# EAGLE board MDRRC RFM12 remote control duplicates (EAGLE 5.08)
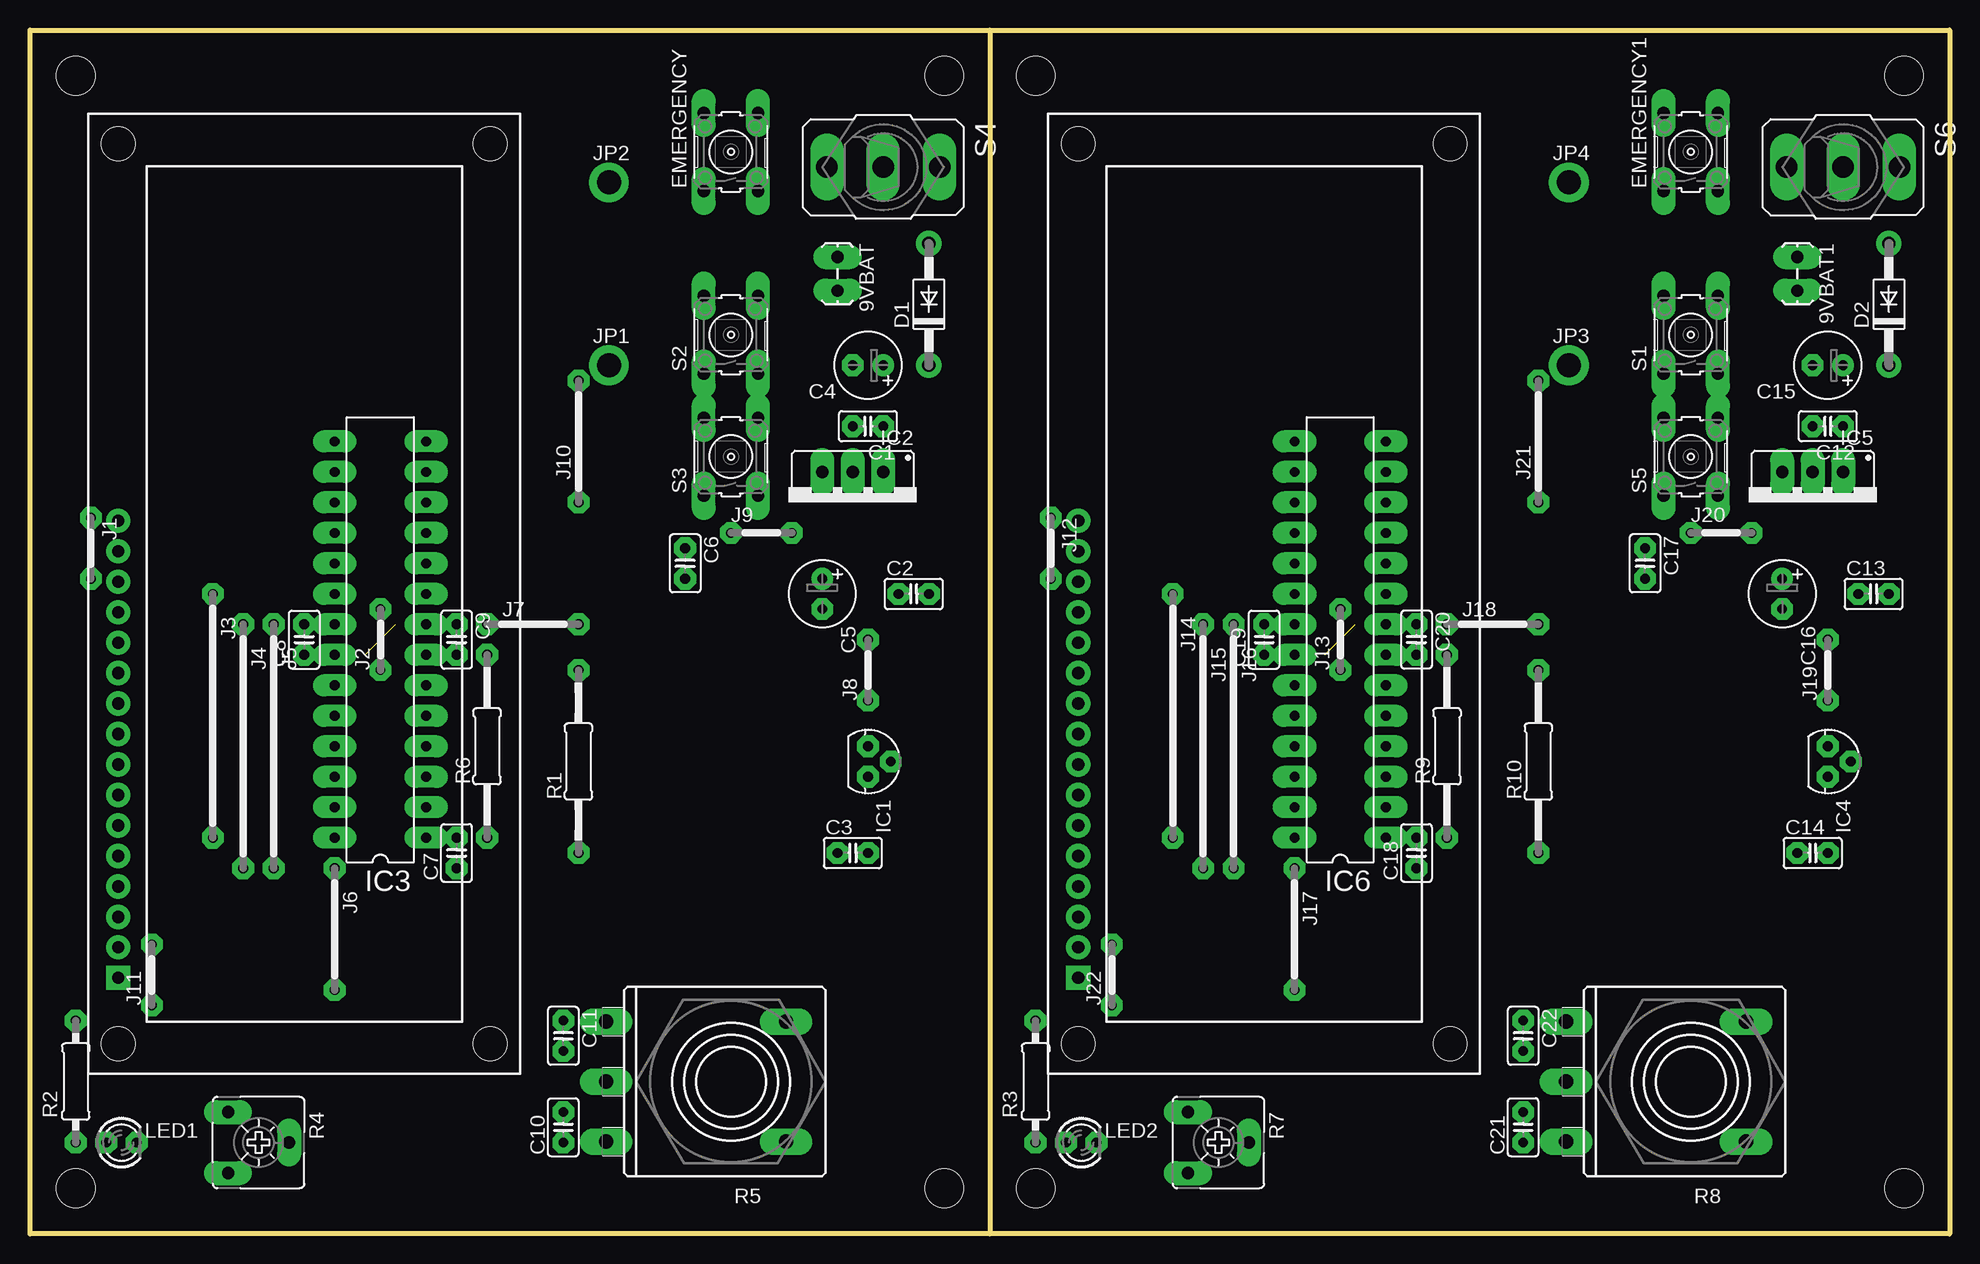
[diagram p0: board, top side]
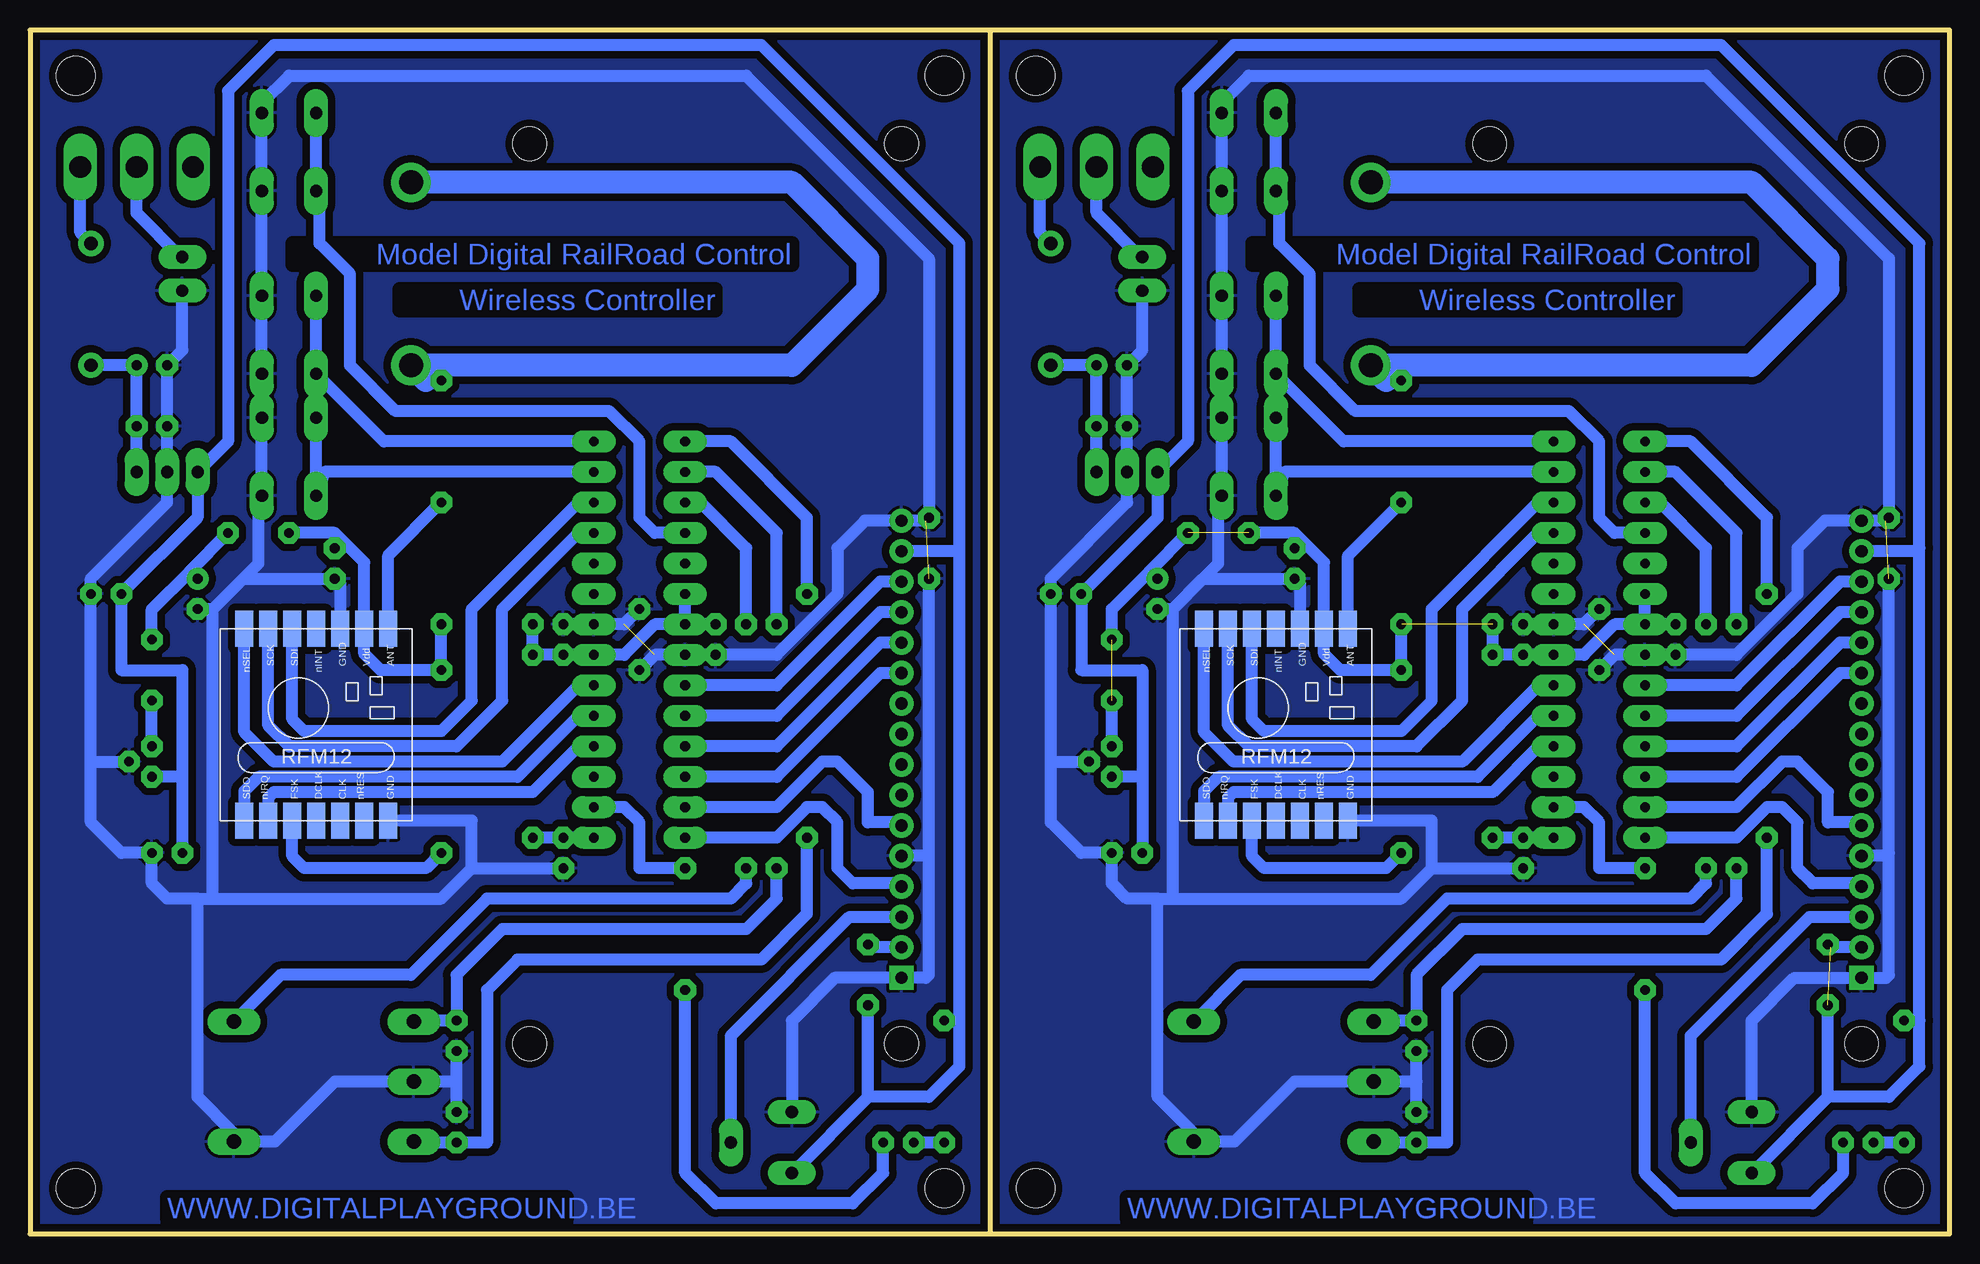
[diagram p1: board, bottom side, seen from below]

Size 160.02 x 100.33 mm. Coordinates in mm from the lower left corner, seen from the top.
Outline: 80.01,100.33 0,100.33 0,0 80.01,0
Outline: 80.01,100.33 160.02,100.33 160.02,0 80.01,0
Outline: 80.01,100.33 80.01,0
Copper layers (1*16): Top 0.8mm / dielectric 1.3mm / Bottom 0.8mm
Design rules "DRC settings smallest": minimum track width 0.8mm, minimum drill 24mil, track to track 0.2mm, track to pad 0.2mm, pad to pad 0.2mm, via to via 0.2mm, smd to smd 8mil, copper to edge 0.3mm, drill to drill 0.3mm, minimum pad ring 0.5mm, minimum via ring 1mm, stop-mask expansion 4mil, vias tented up to drill 0mil, thermal gap 10mil
Holes 3.2 mm at 3.81,96.52 3.81,3.81 76.2,3.81 76.2,96.52 83.82,96.52 83.82,3.81 156.21,3.81 156.21,96.52

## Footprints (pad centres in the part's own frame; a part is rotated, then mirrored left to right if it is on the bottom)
1X02_LOCK_LONGPADS = drill 1.016 long: 1 -0.127,0; 2 2.667,0
C025-025X050 = drill 0.813 octagon: 1 -1.27,0; 2 1.27,0
E2,5-6 = drill 0.813 pad 1.6 round: + -1.27,0 | drill 0.813 pad 1.6 octagon: - 1.27,0
DO41-10 = drill 1.118 round: A 5.08,0; C -5.08,0
B3F-10XX = drill 1.016 long: 1 -3.251,2.261; 2 3.251,2.261; 3 -3.251,-2.261; 4 3.251,-2.261
78LXX = drill 0.813 octagon: GND 0,1.905; IN 1.27,0; OUT -1.27,0
78XXS = drill 1.016 long: GND 0,-2.54; IN -2.54,-2.54; OUT 2.54,-2.54
DIL28-3 = drill 0.813 long: 1 -16.51,-3.81; 2 -13.97,-3.81; 3 -11.43,-3.81; 4 -8.89,-3.81; 5 -6.35,-3.81; 6 -3.81,-3.81; 7 -1.27,-3.81; 8 1.27,-3.81; 9 3.81,-3.81; 10 6.35,-3.81; 11 8.89,-3.81; 12 11.43,-3.81; 13 13.97,-3.81; 14 16.51,-3.81; 15 16.51,3.81; 16 13.97,3.81; 17 11.43,3.81; 18 8.89,3.81; 19 6.35,3.81; 20 3.81,3.81; 21 1.27,3.81; 22 -1.27,3.81; 23 -3.81,3.81; 24 -6.35,3.81; 25 -8.89,3.81; 26 -11.43,3.81; 27 -13.97,3.81; 28 -16.51,3.81
05 = drill 0.813 pad 1.6 octagon: 1 -2.54,0; 2 2.54,0
20 = drill 0.813 pad 1.6 octagon: 1 -10.16,0; 2 10.16,0
10 = drill 0.813 pad 1.6 octagon: 1 -5.08,0; 2 5.08,0
07 = drill 0.813 pad 1.6 octagon: 1 -3.81,0; 2 3.81,0
1X01_2MM = drill 2 pad 3.302 round: 1 0,0
LED3MM = drill 0.813 octagon: A -1.27,0; K 1.27,0
0207/15 = drill 0.813 octagon: 1 -7.62,0; 2 7.62,0
0207/10 = drill 0.813 octagon: 1 -5.08,0; 2 5.08,0
CA6V = drill 1.016 long: A -2.54,-2.54; E 2.54,-2.54; S 0,2.54
PC16SV = drill 1.2 long: 1A -5,10.4; 1E 5,10.4; 1S 0,10.4; S1 -5,-4.6; S2 5,-4.6
M9040P = drill 1.803 long: 1 0,4.699; 2 0,0; 3 0,-4.699
RFM12 = smd 1.5 x 3: 1 -5,-10; 2 -3,-10; 3 -1,-10; 4 1,-10; 5 3,-10; 6 5,-10; 7 7,-10; 8 7,6; 9 5,6; 10 3,6; 11 1,6; 12 -1,6; 13 -3,6; 14 -5,6
LCD-16X2 = drill 1.016 square: 1 -32,15.5 | drill 1.016 round: 2 -29.46,15.5; 3 -26.92,15.5; 4 -24.38,15.5; 5 -21.84,15.5; 6 -19.3,15.5; 7 -16.76,15.5; 8 -14.22,15.5; 9 -11.68,15.5; 10 -9.14,15.5; 11 -6.6,15.5; 12 -4.06,15.5; 13 -1.52,15.5; 14 1.02,15.5; 15 3.56,15.5; 16 6.1,15.5 | hole 2.8: -37.5,15.5; -37.5,-15.5; 37.5,15.5; 37.5,-15.5

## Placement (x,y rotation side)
9VBAT  [1X02_LOCK_LONGPADS]  67.31,81.28 270 top
9VBAT1  [1X02_LOCK_LONGPADS]  147.32,81.28 270 top
C1  100nF  [C025-025X050]  69.85,67.31 180 top
C2  100nF  [C025-025X050]  73.66,53.34 0 top
C3  100nF  [C025-025X050]  68.58,31.75 0 top
C4  10uF  [E2,5-6]  69.85,72.39 180 top
C5  10uF  [E2,5-6]  66.04,53.34 270 top
C6  100nF  [C025-025X050]  54.61,55.88 270 top
C7  100nF  [C025-025X050]  35.56,31.75 90 top
C8  100nF  [C025-025X050]  22.86,49.53 90 top
C9  100nF  [C025-025X050]  35.56,49.53 270 top
C10  100nF  [C025-025X050]  44.45,8.89 90 top
C11  100nF  [C025-025X050]  44.45,16.51 270 top
C12  100nF  [C025-025X050]  149.86,67.31 180 top
C13  100nF  [C025-025X050]  153.67,53.34 0 top
C14  100nF  [C025-025X050]  148.59,31.75 0 top
C15  10uF  [E2,5-6]  149.86,72.39 180 top
C16  10uF  [E2,5-6]  146.05,53.34 270 top
C17  100nF  [C025-025X050]  134.62,55.88 270 top
C18  100nF  [C025-025X050]  115.57,31.75 90 top
C19  100nF  [C025-025X050]  102.87,49.53 90 top
C20  100nF  [C025-025X050]  115.57,49.53 270 top
C21  100nF  [C025-025X050]  124.46,8.89 90 top
C22  100nF  [C025-025X050]  124.46,16.51 270 top
D1  1N4004  [DO41-10]  74.93,77.47 90 top
D2  1N4004  [DO41-10]  154.94,77.47 90 top
EMERGENCY  [B3F-10XX]  58.42,90.17 90 top
EMERGENCY1  [B3F-10XX]  138.43,90.17 90 top
IC1  78L33  [78LXX]  69.85,39.37 270 top
IC2  7805  [78XXS]  68.58,60.96 180 top
IC3  MEGA8-P  [DIL28-3]  29.21,49.53 90 top
IC4  78L33  [78LXX]  149.86,39.37 270 top
IC5  7805  [78XXS]  148.59,60.96 180 top
IC6  MEGA8-P  [DIL28-3]  109.22,49.53 90 top
J1  J5MM  [05]  5.08,57.15 270 top
J2  J5MM  [05]  29.21,49.53 90 top
J3  J20MM  [20]  15.24,43.18 270 top
J4  J20MM  [20]  17.78,40.64 270 top
J5  J20MM  [20]  20.32,40.64 270 top
J6  J10MM  [10]  25.4,25.4 270 top
J7  J7MM  [07]  41.91,50.8 0 top
J8  J5MM  [05]  69.85,46.99 90 top
J9  J5MM  [05]  60.96,58.42 0 top
J10  J10MM  [10]  45.72,66.04 90 top
J11  J5MM  [05]  10.16,21.59 90 top
J12  J5MM  [05]  85.09,57.15 270 top
J13  J5MM  [05]  109.22,49.53 90 top
J14  J20MM  [20]  95.25,43.18 270 top
J15  J20MM  [20]  97.79,40.64 270 top
J16  J20MM  [20]  100.33,40.64 270 top
J17  J10MM  [10]  105.41,25.4 270 top
J18  J7MM  [07]  121.92,50.8 0 top
J19  J5MM  [05]  149.86,46.99 90 top
J20  J5MM  [05]  140.97,58.42 0 top
J21  J10MM  [10]  125.73,66.04 90 top
J22  J5MM  [05]  90.17,21.59 90 top
JP1  M01PTH_2MM  [1X01_2MM]  48.26,72.39 0 top
JP2  M01PTH_2MM  [1X01_2MM]  48.26,87.63 0 top
JP3  M01PTH_2MM  [1X01_2MM]  128.27,72.39 0 top
JP4  M01PTH_2MM  [1X01_2MM]  128.27,87.63 0 top
LED1  [LED3MM]  7.62,7.62 0 top
LED2  [LED3MM]  87.63,7.62 0 top
R1  1K  [0207/15]  45.72,39.37 90 top
R2  1K  [0207/10]  3.81,12.7 90 top
R3  1K  [0207/10]  83.82,12.7 90 top
R4  [CA6V]  19.05,7.62 270 top
R5  PC16SV  [PC16SV]  58.42,12.7 90 top
R6  10K  [0207/15]  38.1,40.64 90 top
R7  [CA6V]  99.06,7.62 270 top
R8  PC16SV  [PC16SV]  138.43,12.7 90 top
R9  10K  [0207/15]  118.11,40.64 90 top
R10  1K  [0207/15]  125.73,39.37 90 top
S1  [B3F-10XX]  138.43,74.93 90 top
S2  [B3F-10XX]  58.42,74.93 90 top
S3  [B3F-10XX]  58.42,64.77 90 top
S4  [M9040P]  71.12,88.9 270 top
S5  [B3F-10XX]  138.43,64.77 90 top
S6  [M9040P]  151.13,88.9 270 top
U$1  RFM12_SMDSMD  [RFM12]  57.15,44.45 0 bottom
U$2  LCD-16X2  [LCD-16X2]  22.86,53.34 90 top
U$3  RFM12_SMDSMD  [RFM12]  137.16,44.45 0 bottom
U$4  LCD-16X2  [LCD-16X2]  102.87,53.34 90 top

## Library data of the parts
9VBAT 9VBAT1 JP1-JP4 U$2 U$4 = SparkFun
C1-C3 C6-C14 C17-C22 R1 R6 R9 R10 = rcl
C4 C5 C15 C16 R2 R3 = resistor
D1 D2 = diode
EMERGENCY EMERGENCY1 S1-S3 S5 = switch-omron
IC1 IC2 IC4 IC5 = v-reg
IC3 IC6 = atmel
J1-J22 = jumper
LED1 LED2 = led
R4 R7 = pot
R5 R8 = piher
S4 S6 = switch
U$1 U$3 = rfm_12

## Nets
+3V1: C16.+ C17.1 C19.2 C20.2 IC4.OUT IC6.7 IC6.20 IC6.21 J18.1 J18.2 J19.1 J19.2 J20.1 J20.2 R9.2 R10.2 U$3.9
+3V3: C5.+ C6.1 C8.2 C9.2 IC1.OUT IC3.7 IC3.20 IC3.21 J7.1 J7.2 J8.1 J8.2 J9.1 J9.2 R1.2 R6.2 U$1.9
+5V: C2.1 C3.1 IC1.IN IC2.OUT J11.1 J11.2 R2.2 R4.E U$2.2 U$2.15
+5V1: C13.1 C14.1 IC4.IN IC5.OUT J22.1 J22.2 R3.2 R7.E U$4.2 U$4.15
GND: 9VBAT.2 C1.2 C2.2 C3.2 C4.- C5.- C6.2 C7.1 C8.1 C9.1 C10.2 C11.2 EMERGENCY.3 EMERGENCY.4 IC1.GND IC2.GND IC3.8 IC3.22 J1.1 J1.2 J2.1 J2.2 R4.A R5.1S R5.S1 S2.3 S2.4 S3.3 S3.4 U$1.7 U$1.10 U$2.1 U$2.5 U$2.16
GND1: 9VBAT1.2 C12.2 C13.2 C14.2 C15.- C16.- C17.2 C18.1 C19.1 C20.1 C21.2 C22.2 EMERGENCY1.3 EMERGENCY1.4 IC4.GND IC5.GND IC6.8 IC6.22 J12.1 J12.2 J13.1 J13.2 R7.A R8.1S R8.S1 S1.3 S1.4 S5.3 S5.4 U$3.7 U$3.10 U$4.1 U$4.5 U$4.16
N$1: D1.A S4.1
N$2: C1.1 C4.+ D1.C IC2.IN
N$3: 9VBAT.1 S4.2
N$4: IC3.2 J6.1
N$5: C7.2 IC3.1 R6.1
N$6: R4.S U$2.3
N$7: J5.2 R5.S2
N$8: LED1.A R2.1
N$9: J6.2 LED1.K
N$10: J10.2 JP1.1 JP2.1
N$11: R1.1 U$1.3
N$12: IC3.28 U$2.4
N$13: IC3.27 U$2.6
N$14: IC3.23 U$2.14
N$15: IC3.24 U$2.13
N$16: IC3.25 U$2.12
N$17: IC3.26 U$2.11
N$18: IC3.12 U$1.12
N$19: IC3.5 U$1.1
N$20: IC3.11 U$1.13
N$21: IC3.6 U$1.14
N$22: IC3.4 U$1.2
N$23: J10.1 U$1.8
N$24: EMERGENCY.1 EMERGENCY.2 IC3.18
N$25: IC3.15 J3.1
N$26: IC3.14 S2.1 S2.2
N$27: IC3.13 S3.1 S3.2
N$28: IC3.16 J4.1
N$29: IC3.17 J5.1
N$30: C10.1 J3.2 R5.1A
N$31: C11.1 J4.2 R5.1E
N$32: C12.1 C15.+ D2.C IC5.IN
N$33: J21.2 JP3.1 JP4.1
N$34: R10.1 U$3.3
N$35: C18.2 IC6.1 R9.1
N$36: LED2.A R3.1
N$37: IC6.28 U$4.4
N$38: IC6.27 U$4.6
N$39: IC6.23 U$4.14
N$40: IC6.24 U$4.13
N$41: IC6.25 U$4.12
N$42: IC6.26 U$4.11
N$43: IC6.12 U$3.12
N$44: IC6.5 U$3.1
N$45: IC6.11 U$3.13
N$46: IC6.6 U$3.14
N$47: IC6.4 U$3.2
N$48: R7.S U$4.3
N$49: J16.2 R8.S2
N$50: EMERGENCY1.1 EMERGENCY1.2 IC6.18
N$51: IC6.14 S1.1 S1.2
N$52: IC6.13 S5.1 S5.2
N$53: IC6.15 J14.1
N$54: IC6.16 J15.1
N$55: IC6.17 J16.1
N$56: C21.1 J14.2 R8.1A
N$57: C22.1 J15.2 R8.1E
N$58: IC6.2 J17.1
N$59: J17.2 LED2.K
N$60: J21.1 U$3.8
N$61: D2.A S6.1
N$62: 9VBAT1.1 S6.2

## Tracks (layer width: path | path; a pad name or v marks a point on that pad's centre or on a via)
+3V1
  Bottom 1.016: C19.2 IC6.21 | IC6.21 IC6.20 | IC6.21 107.95,50.8 110.49,48.26 IC6.7 C20.2 R9.2 J18.1 | J18.2 R10.2 130.81,46.99 132.16,48.34 U$3.9 132.16,55.96 134.62,58.42 | IC4.OUT J19.1 | J19.2 149.86,52.07 146.69,55.24 | 146.69,55.24 J20.2 | 146.69,55.24 C16.+ | 134.62,58.42 J20.1 | 134.62,58.42 C17.1
+3V3  (3 unrouted)
  Bottom 1.016: C8.2 IC3.21 | IC3.21 IC3.20 | IC3.21 27.94,50.8 30.48,48.26 IC3.7 C9.2 R6.2 J7.1 | J7.2 R1.2 50.8,46.99 52.15,48.34 U$1.9 52.15,55.96 54.61,58.42 | IC1.OUT J8.1 | J8.2 69.85,52.07 66.67,55.24 | 66.67,55.24 J9.2 | 66.67,55.24 C5.+ | 54.61,58.42 J9.1 | 54.61,58.42 C6.1
+5V  (1 unrouted)
  Bottom 1.016: 2.54,17.78 2.54,13.97 5.08,11.43 10.16,11.43 | 2.54,17.78 2.54,57.15 | 67.31,38.1 67.31,46.99 72.39,46.99 C2.1 66.04,59.69 IC2.OUT 63.5,66.04 63.5,95.25 59.69,99.06 19.05,99.06 2.54,82.55 2.54,57.15 | 67.31,38.1 IC1.IN | 67.31,38.1 C3.1 | U$2.15 2.79,56.9 2.54,57.15 | 7.87,23.88 U$2.2 9.91,23.88 J11.2 | 10.16,11.43 R4.E | 10.16,11.43 J11.1 | 2.54,17.78 R2.2
+5V1
  Bottom 1.016: 82.55,17.78 82.55,13.97 85.09,11.43 90.17,11.43 | 82.55,17.78 82.55,57.15 | 147.32,38.1 147.32,46.99 152.4,46.99 C13.1 146.05,59.69 IC5.OUT 143.51,66.04 143.51,95.25 139.7,99.06 99.06,99.06 82.55,82.55 82.55,57.15 | 147.32,38.1 IC4.IN | 147.32,38.1 C14.1 | U$4.15 82.8,56.9 82.55,57.15 | 87.88,23.88 U$4.2 89.92,23.88 J22.2 | 90.17,11.43 R7.E | 90.17,11.43 J22.1 | 82.55,17.78 R3.2
GND  (2 unrouted)
  Bottom 1.016: J2.2 30.48,50.8 IC3.8 C9.1 | J2.1 27.94,48.26 IC3.22 C8.1 17.78,48.26 12.7,53.34 12.7,57.15 10.41,59.44 U$2.16 5.33,59.44 J1.1 5.08,81.28 20.32,96.52 58.42,96.52 60.68,94.26 S3.3 | C10.2 44.45,12.7 | 44.45,12.7 C11.2 | 44.45,12.7 R5.1S 54.61,12.7 59.61,7.7 R5.S1 63.02,8.41 66.04,11.43 66.04,27.94 | EMERGENCY.4 EMERGENCY.3 S2.4 S2.3 S3.4 S3.3 | U$1.7 43.18,34.45 43.18,30.48 | S3.3 60.96,62.51 60.96,55.88 62.23,54.61 | 64.77,52.07 62.23,54.61 | 64.77,52.07 C5.- | 64.77,27.94 64.77,52.07 | 74.93,39.37 IC1.GND | 74.93,39.37 74.93,34.29 72.39,31.75 C3.2 69.85,29.21 68.58,27.94 66.04,27.94 | 66.04,27.94 64.77,27.94 | 74.93,39.37 C2.2 74.93,54.61 68.58,60.96 IC2.GND C1.2 C4.- 67.31,73.66 9VBAT.2 | 64.77,27.94 45.72,27.94 43.18,30.48 | 5.08,31.75 5.08,21.59 5.33,21.34 U$2.1 12.95,21.34 16.51,17.78 R4.A | U$2.5 5.33,31.5 5.08,31.75 | 5.08,31.75 J1.2 | 43.18,30.48 C7.1 | U$1.10 54.15,54.15 C6.2 62.23,54.61
  pour Bottom (isolate 0.61): 0,100.33 80.01,100.33 80.01,0 0,0
  pour Bottom (isolate 0.61): 0,100.33 80.01,100.33 80.01,0 0,0
GND1  (2 unrouted)
  Bottom 1.016: J13.2 110.49,50.8 IC6.8 C20.1 | J13.1 107.95,48.26 IC6.22 C19.1 97.79,48.26 92.71,53.34 92.71,57.15 90.42,59.44 U$4.16 85.34,59.44 J12.1 85.09,81.28 100.33,96.52 138.43,96.52 140.69,94.26 S5.3 | C21.2 124.46,12.7 | 124.46,12.7 C22.2 | 124.46,12.7 R8.1S 134.62,12.7 139.62,7.7 R8.S1 143.03,8.41 146.05,11.43 146.05,27.94 | EMERGENCY1.4 EMERGENCY1.3 S1.4 S1.3 S5.4 S5.3 | U$3.7 123.19,34.45 123.19,30.48 | S5.3 140.97,62.51 140.97,55.88 142.24,54.61 | 144.78,52.07 142.24,54.61 | 144.78,52.07 C16.- | 144.78,27.94 144.78,52.07 | 154.94,39.37 IC4.GND | 154.94,39.37 154.94,34.29 152.4,31.75 C14.2 149.86,29.21 148.59,27.94 146.05,27.94 | 146.05,27.94 144.78,27.94 | 154.94,39.37 C13.2 154.94,54.61 148.59,60.96 IC5.GND C12.2 C15.- 147.32,73.66 9VBAT1.2 | 144.78,27.94 125.73,27.94 123.19,30.48 | 85.09,31.75 85.09,21.59 85.34,21.34 U$4.1 92.96,21.34 96.52,17.78 R7.A | U$4.5 85.34,31.5 85.09,31.75 | 85.09,31.75 J12.2 | 123.19,30.48 C18.1 | U$3.10 134.16,54.15 C17.2 142.24,54.61
  pour Bottom (isolate 0.61): 80.01,100.33 160.02,100.33 160.02,0 80.01,0
N$1
  Bottom 1.016: S4.1 75.82,83.44 D1.A
N$2
  Bottom 1.016: IC2.IN C1.1 C4.+ D1.C
N$3
  Bottom 1.016: 9VBAT.1 67.44,81.41 71.12,85.09 S4.2
N$4
  Bottom 1.016: IC3.2 30.48,35.56 29.21,34.29 29.21,30.48 J6.1
N$5
  Bottom 1.016: IC3.1 C7.2 R6.1
N$6
  Bottom 1.016: U$2.3 11.68,26.42 21.59,16.51 R4.S
N$7
  Bottom 1.016: J5.2 20.32,29.21 21.59,27.94 41.91,27.94 48.26,21.59 59.13,21.59 R5.S2
N$8
  Bottom 1.016: R2.1 LED1.A
N$9
  Bottom 1.016: J6.2 25.4,5.08 22.86,2.54 11.43,2.54 8.89,5.08 LED1.K
N$10
  Bottom 1.016: 46.99,71.12 J10.2
  Bottom 1.93: 46.99,71.12 JP1.1 16.51,72.39 10.16,78.74 10.16,81.28 16.51,87.63 JP2.1
N$11
  Bottom 1.016: U$1.3 58.15,31.48 57.15,30.48 46.99,30.48 R1.1
N$12
  Bottom 1.016: IC3.28 17.78,33.02 15.24,35.56 13.97,35.56 12.7,34.29 12.7,30.48 11.43,29.21 7.61,29.21 U$2.4
N$13
  Bottom 1.016: IC3.27 17.78,35.56 13.97,39.37 12.7,39.37 10.16,36.83 10.16,34.29 7.61,34.29 U$2.6
N$14
  Bottom 1.016: U$2.14 9.14,54.36 17.78,45.72 IC3.23
N$15
  Bottom 1.016: U$2.13 9.14,51.82 17.78,43.18 IC3.24
N$16
  Bottom 1.016: U$2.12 9.14,49.28 17.78,40.64 IC3.25
N$17
  Bottom 1.016: U$2.11 9.14,46.74 17.78,38.1 IC3.26
N$18
  Bottom 1.016: U$1.12 58.15,42.91 57.15,41.91 45.72,41.91 43.18,44.45 43.18,52.07 34.29,60.96 IC3.12
N$19
  Bottom 1.016: U$1.1 62.15,36.91 60.96,38.1 39.37,38.1 34.29,43.18 IC3.5
N$20
  Bottom 1.016: U$1.13 60.15,42.37 58.42,40.64 44.45,40.64 40.64,44.45 40.64,52.07 34.29,58.42 IC3.11
N$21
  Bottom 1.016: U$1.14 62.15,41.83 59.69,39.37 40.64,39.37 34.29,45.72 IC3.6
N$22
  Bottom 1.016: IC3.4 34.29,40.64 38.1,36.83 59.69,36.83 60.15,36.37 U$1.2
N$23
  Bottom 1.016: U$1.8 50.15,56.53 J10.1
N$24
  Bottom 1.016: EMERGENCY.2 EMERGENCY.1 55.88,86.64 55.88,82.55 53.34,80.01 53.34,72.39 49.53,68.58 31.75,68.58 29.21,66.04 29.21,59.69 27.94,58.42 IC3.18
N$25
  Bottom 1.016: IC3.15 21.59,66.04 15.24,59.69 J3.1
N$26
  Bottom 1.016: S2.2 S2.1 50.52,66.04 IC3.14
N$27
  Bottom 1.016: S3.2 S3.1 55.45,63.5 IC3.13
N$28
  Bottom 1.016: IC3.16 22.86,63.5 17.78,58.42 J4.1
N$29
  Bottom 1.016: IC3.17 24.13,60.96 20.32,57.15 J5.1
N$30
  Bottom 1.016: R5.1A 47.94,7.62 C10.1 41.91,7.62 41.91,20.32 39.37,22.86 19.05,22.86 15.24,26.67 J3.2
N$31
  Bottom 1.016: R5.1E 47.94,17.78 C11.1 44.45,21.59 40.64,25.4 20.32,25.4 17.78,27.94 J4.2
N$32
  Bottom 1.016: IC5.IN C12.1 C15.+ D2.C
N$33
  Bottom 1.016: 127,71.12 J21.2
  Bottom 1.93: 127,71.12 JP3.1 96.52,72.39 90.17,78.74 90.17,81.28 96.52,87.63 JP4.1
N$34
  Bottom 1.016: U$3.3 138.16,31.48 137.16,30.48 127,30.48 R10.1
N$35
  Bottom 1.016: IC6.1 C18.2 R9.1
N$36
  Bottom 1.016: R3.1 LED2.A
N$37
  Bottom 1.016: IC6.28 97.79,33.02 95.25,35.56 93.98,35.56 92.71,34.29 92.71,30.48 91.44,29.21 87.62,29.21 U$4.4
N$38
  Bottom 1.016: IC6.27 97.79,35.56 93.98,39.37 92.71,39.37 90.17,36.83 90.17,34.29 87.62,34.29 U$4.6
N$39
  Bottom 1.016: U$4.14 89.15,54.36 97.79,45.72 IC6.23
N$40
  Bottom 1.016: U$4.13 89.15,51.82 97.79,43.18 IC6.24
N$41
  Bottom 1.016: U$4.12 89.15,49.28 97.79,40.64 IC6.25
N$42
  Bottom 1.016: U$4.11 89.15,46.74 97.79,38.1 IC6.26
N$43
  Bottom 1.016: U$3.12 138.16,42.91 137.16,41.91 125.73,41.91 123.19,44.45 123.19,52.07 114.3,60.96 IC6.12
N$44
  Bottom 1.016: U$3.1 142.16,36.91 140.97,38.1 119.38,38.1 114.3,43.18 IC6.5
N$45
  Bottom 1.016: U$3.13 140.16,42.37 138.43,40.64 124.46,40.64 120.65,44.45 120.65,52.07 114.3,58.42 IC6.11
N$46
  Bottom 1.016: U$3.14 142.16,41.83 139.7,39.37 120.65,39.37 114.3,45.72 IC6.6
N$47
  Bottom 1.016: IC6.4 114.3,40.64 118.11,36.83 139.7,36.83 140.16,36.37 U$3.2
N$48
  Bottom 1.016: U$4.3 91.69,26.42 101.6,16.51 R7.S
N$49
  Bottom 1.016: J16.2 100.33,29.21 101.6,27.94 121.92,27.94 128.27,21.59 139.14,21.59 R8.S2
N$50
  Bottom 1.016: EMERGENCY1.2 EMERGENCY1.1 135.89,86.64 135.89,82.55 133.35,80.01 133.35,72.39 129.54,68.58 111.76,68.58 109.22,66.04 109.22,59.69 107.95,58.42 IC6.18
N$51
  Bottom 1.016: S1.2 S1.1 130.53,66.04 IC6.14
N$52
  Bottom 1.016: S5.2 S5.1 135.46,63.5 IC6.13
N$53
  Bottom 1.016: IC6.15 101.6,66.04 95.25,59.69 J14.1
N$54
  Bottom 1.016: IC6.16 102.87,63.5 97.79,58.42 J15.1
N$55
  Bottom 1.016: IC6.17 104.14,60.96 100.33,57.15 J16.1
N$56
  Bottom 1.016: R8.1A 127.95,7.62 C21.1 121.92,7.62 121.92,20.32 119.38,22.86 99.06,22.86 95.25,26.67 J14.2
N$57
  Bottom 1.016: R8.1E 127.95,17.78 C22.1 124.46,21.59 120.65,25.4 100.33,25.4 97.79,27.94 J15.2
N$58
  Bottom 1.016: IC6.2 110.49,35.56 109.22,34.29 109.22,30.48 J17.1
N$59
  Bottom 1.016: J17.2 105.41,5.08 102.87,2.54 91.44,2.54 88.9,5.08 LED2.K
N$60
  Bottom 1.016: U$3.8 130.16,56.53 J21.1
N$61
  Bottom 1.016: S6.1 155.83,83.44 D2.A
N$62
  Bottom 1.016: 9VBAT1.1 147.45,81.41 151.13,85.09 S6.2

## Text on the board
Bottom: Model Digital RailRoad Control | Model Digital RailRoad Control | Wireless Controller | Wireless Controller | WWW.DIGITALPLAYGROUND.BE | WWW.DIGITALPLAYGROUND.BE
